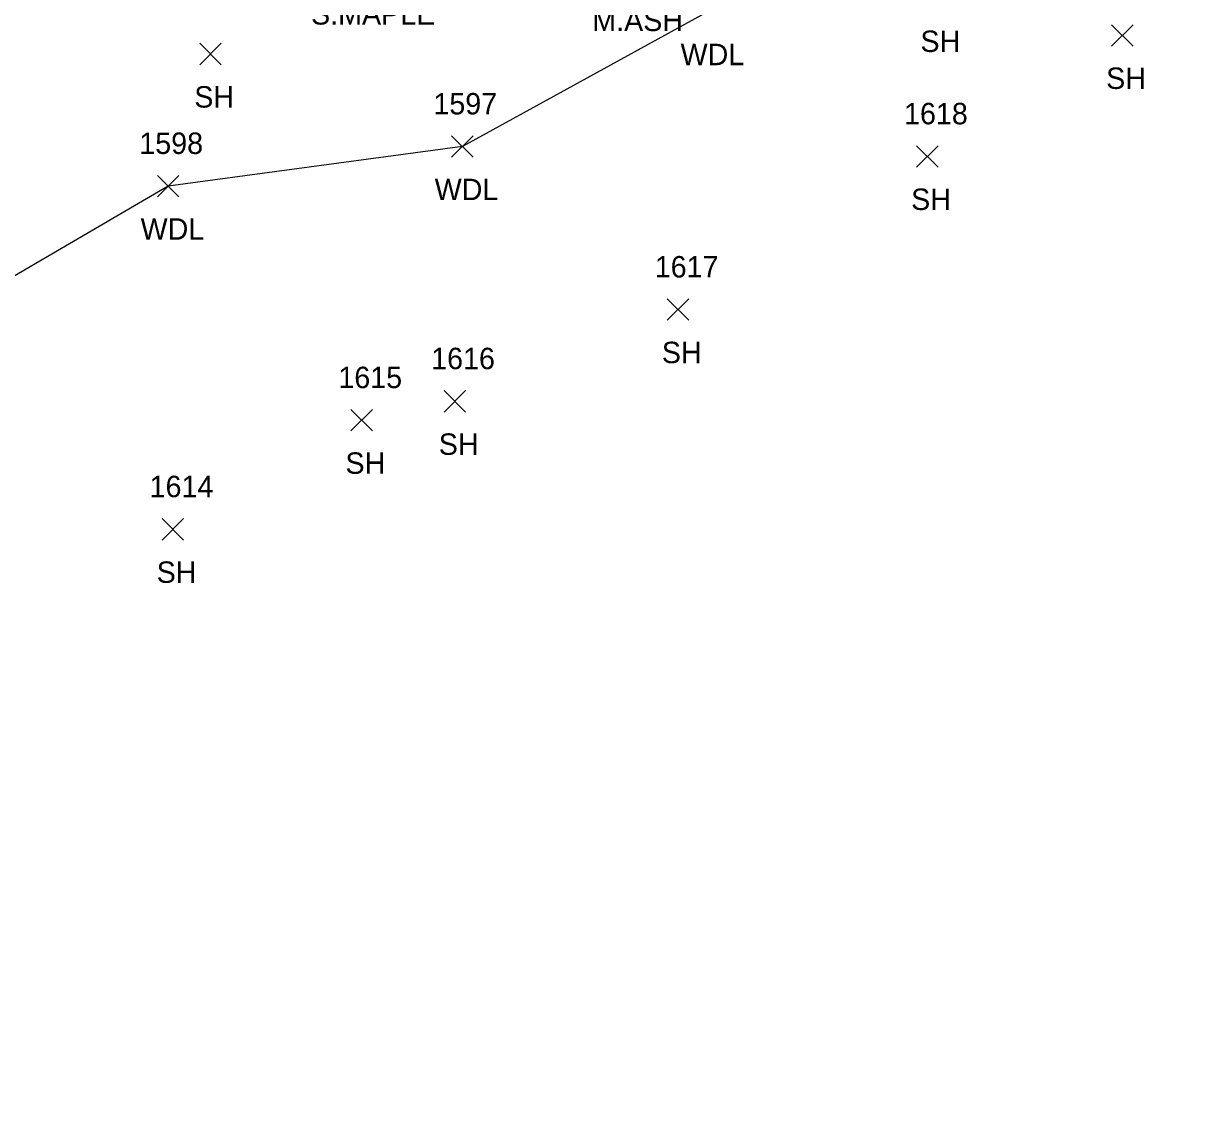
# Model space of a CAD drawing. Extents: x 1621633 to 1624015, y 417863 to 420979.
# Drawn here: x 1621891.2 to 1622001, y 417881.2 to 417982.6 of the extents above; entities that cross this region are included whole.
import ezdxf

# ---------------------------------------------------------------- set-up
doc = ezdxf.new("R2010")
doc.units = 0
for name, color, linetype in [('L_A', 7, 'Continuous'), ('L_C', 7, 'Continuous'), ('L_I', 7, 'Continuous'), ('L_TIC', 7, 'Continuous'), ('LAWA', 7, 'Continuous')]:
    doc.layers.add(name, color=color, linetype=linetype)

msp = doc.modelspace()

# ---------------------------------------------------------------- linework, layer by layer
at = {"layer": 'L_TIC'}
for points in [[(1621992.8, 417980.54), (1621994.8, 417982.54)], [(1621994.8, 417980.54), (1621992.8, 417982.54)], [(1621907.7, 417978.8), (1621909.7, 417980.8)], [(1621909.7, 417978.8), (1621907.7, 417980.8)], [(1621931.2, 417970.16), (1621933.2, 417972.16)], [(1621933.2, 417970.16), (1621931.2, 417972.16)], [(1621974.6, 417969.24), (1621976.6, 417971.24)], [(1621976.6, 417969.24), (1621974.6, 417971.24)], [(1621903.75, 417966.47), (1621905.75, 417968.47)], [(1621905.75, 417966.47), (1621903.75, 417968.47)], [(1621951.33, 417954.94), (1621953.33, 417956.94)], [(1621953.33, 417954.94), (1621951.33, 417956.94)], [(1621930.51, 417946.38), (1621932.51, 417948.38)], [(1621932.51, 417946.38), (1621930.51, 417948.38)], [(1621921.8, 417944.61), (1621923.8, 417946.61)], [(1621923.8, 417944.61), (1621921.8, 417946.61)], [(1621904.18, 417934.43), (1621906.18, 417936.43)], [(1621906.18, 417934.43), (1621904.18, 417936.43)]]:
    msp.add_lwpolyline(points, dxfattribs=at)
at = {"layer": 'LAWA'}
msp.add_lwpolyline([(1622001, 418030.11), (1621986.32, 418023.66), (1621975.51, 418000.43), (1621955.16, 417983.76), (1621932.2, 417971.16), (1621904.75, 417967.47), (1621879.49, 417952.72), (1621860.19, 417941.59), (1621844.31, 417921.47), (1621821.12, 417913.63), (1621798.12, 417906.33), (1621768.53, 417901.53), (1621742.57, 417889.76), (1621727.86, 417881.17)], dxfattribs=at)

# ---------------------------------------------------------------- texts
at = {"layer": 'L_A'}
for s, p in [('SH', (1621974.96, 417979.99)), ('WDL', (1621952.57, 417978.76)), ('SH', (1621992.29, 417976.54)), ('SH', (1621907.18, 417974.8)), ('WDL', (1621929.62, 417966.16)), ('SH', (1621974.09, 417965.24)), ('WDL', (1621902.17, 417962.47)), ('SH', (1621950.82, 417950.94)), ('SH', (1621930, 417942.38)), ('SH', (1621921.29, 417940.61)), ('SH', (1621903.67, 417930.43))]:
    msp.add_text(s, height=2, dxfattribs=at).set_placement(p)
at = {"layer": 'L_C'}
for s, p in [('S.MAPLE', (1621918.08, 417982.55)), ('M.ASH', (1621944.33, 417981.94))]:
    msp.add_text(s, height=2, dxfattribs=at).set_placement(p)
at = {"layer": 'L_I'}
for s, p in [('1597', (1621929.5, 417974.16)), ('1618', (1621973.43, 417973.24)), ('1598', (1621902.05, 417970.47)), ('1617', (1621950.16, 417958.94)), ('1616', (1621929.29, 417950.38)), ('1615', (1621920.63, 417948.61)), ('1614', (1621903.01, 417938.43))]:
    msp.add_text(s, height=2, dxfattribs=at).set_placement(p)

doc.saveas('drawing.dxf')
